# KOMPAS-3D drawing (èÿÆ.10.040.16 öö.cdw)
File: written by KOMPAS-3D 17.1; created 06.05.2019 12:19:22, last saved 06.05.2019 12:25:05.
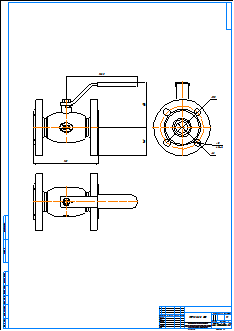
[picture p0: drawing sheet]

Sheet 1: A1, portrait

Title block, sheet 1: name: КШТ.10.040.16 ФФ; material: Внимание! Данный продукт является объектом авторского права ООО «Торговый Дом АДЛ». / Запрещается изменение, копирование, распространение / (в том числе путем копирования на другие сайты и ресурсы в Интернете) / или любое иное использование информации и объектов без предварительного / согласия правообладателя (ООО «Торговый Дом АДЛ»).; sheets: 1; organisation: ООО "Торговый дом АДЛ"; sheet format: A1; stored path: C:\Users\tra\Desktop\2д чертежи\Шаровые краны БИВАЛ\КШ_Бивал_серия_10\KOMPAS 2D\КШТ.10.040.16 ФФ.cdw

Views: Вид 1, Проекционный вид 2, Проекционный вид 3
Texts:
  user
Dimensions and other numbers on the sheet: 116; 72,5; 165; 110; 182,5; 32; 18; 4 Отв.; 1:1; 1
